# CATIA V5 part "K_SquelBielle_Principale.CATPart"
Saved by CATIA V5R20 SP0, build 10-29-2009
Part number: Squelette_bielle_principale
Publications: "Plan_bielle_principale", "Axe_pivot_1", "Axe_pivot_2", "Axe_pivot_3", "Droite_bielle_principale_2", "Droite_bielle_principale_1"
Bounding box of the stored display mesh (mm): x -649.987 to -88.995, y -40 to 0, z 51.091 to 179.845
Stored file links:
  G:\Khaled_CFAO_2011\ST2M\ST2M_GR2\jcoetard\Khaled\CAD_CATIA\K_SquelBielle_Principale.CATPart
  G:\Khaled_CFAO_2011\ST2M\ST2M_GR2\jcoetard\Khaled\CAD_CATIA\K_Squelette.CATProduct
  G:\Khaled_CFAO_2011\ST2M\ST2M_GR2\jcoetard\jcoetard\Maquette_jcoetard\Squelette_ecrou.CATPart
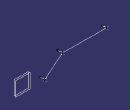
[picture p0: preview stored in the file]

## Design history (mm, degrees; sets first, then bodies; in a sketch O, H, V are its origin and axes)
Set1
  Plane1 "Plan_bielle_motrice": linked copy from another document
  Point1 to Point3: linked copy from another document
Set2 "Set géométrique"
  Plane2 "Plan_bielle_principale": type Offset, RefPlane Plane1, Offset 15, reversed
  Line1 "Axe_pivot_1": type Normal, RefPoint Point1, RefSkin Plane2, Start 0, End 40
  Line2 "Axe_pivot_2": type Normal, RefPoint Point2, RefSkin Plane2, Start 0, End 40
  Line3 "Axe_pivot_3": type Normal, RefPoint Point3, RefSkin Plane2, Start 0, End 40
  Line4 "Droite_bielle_principale_1": type PtPt, FirstPoint Point1, SecondPoint Point2
  Line5 "Droite_bielle_principale_2": type PtPt, FirstPoint Point2, SecondPoint Point3
Body1 (main body)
